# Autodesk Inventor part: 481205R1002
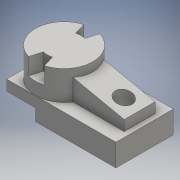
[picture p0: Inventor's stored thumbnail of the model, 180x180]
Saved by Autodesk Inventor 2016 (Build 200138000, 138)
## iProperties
Created: 2018-12
Part Number: 481205R1002
Material: 일반
Document SubType Name: Modeling
Designer: USER
Density: 1 g/cm^3
Appearance: 기본값
Author: USER
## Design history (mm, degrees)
sketch "스케치1"
  geometry: L1 (-78, 41)-(78, 41); L2 (78, 41)-(78, -41); L3 (78, -41)-(-78, -41); L4 (-78, -41)-(-78, 41); L5 (-78, 41)-(78, -41); L6 (78, 41)-(-78, -41); 1 further point
  constraints: 12 end point, 2 midpoint, 2 parallel, 1 horizontal, 1 perpendicular
  dimensions: "d5" = 82 distance of L1.end L2.end; "d6" = 156 distance of L2.end L3.end
extrude "돌출1" new body sketch "스케치1" distance "d7" = 15; taper "d8" = 0 deg
sketch "스케치2"
  geometry: L1 (78, 41)-(-78, 41) reference; L2 (-78, -41)-(78, -41) reference; L3 (-78, 41)-(37, 41); L4 (37, 41)-(37, -41); L5 (37, -41)-(-78, -41); L6 (-78, -41)-(-78, 41); 2 further points
  constraints: 8 end point, 2 parallel, 1 horizontal, 1 horizontal alignment, 1 midpoint, 1 perpendicular, 1 point on line
  dimensions: "d9" = 82 distance of L5.end L1.end (derived); "d10" = 115 distance of L1.end L3.end
extrude "돌출2" join sketch "스케치2" distance "d11" = 17; taper "d12" = 0 deg
node "작업 평면1"
sketch "스케치4"
  geometry: L1 (78, 0)-(-78, 0) reference; L2 (37, -15)-(37, -32) reference; L3 (78, -15)-(37, -15) reference; L4 (37, -15)-(37, 43.573); L5 (78, 0)-(78, 42); L6 (78, 42)-(37, 42); L7 (78, 0)-(37, 0); 1 further point
  constraints: 8 end point, 4 point on line, 2 vertical, 1 perpendicular
  dimensions: "d14" = 41 distance from line of L2 L1.start (derived); "d15" = 82 diameter of L5 L4; "d16" = 42 distance of L5.start L5.end
revolve "회전1" sketch "스케치4" stored, may be unused: angle "d17" = 90 deg
sketch "스케치5"
  geometry: L1 (0, 41)-(0, -41) reference; L2 (6.615, 23.07)-(11.301, 39.412); L3 (-6.615, 23.07)-(-11.301, 39.412); L4 (-58.467, 0)-(58.467, 0); C1 r 41 at (0, 0); C2 r 24 at (0, 0); A1 r 41 centre (0, 0) between (0, 41) and (0, -41) reference; A2 r 41 centre (0, 0) between (11.301, 39.412) and (-11.301, 39.412); A3 r 24 centre (0, 0) between (6.615, 23.07) and (-6.615, 23.07); A4 r 24 centre (0, 0) between (-6.615, -23.07) and (6.615, -23.07); 5 further points
  constraints: 7 point on circle, 6 end point, 5 centre point, 3 coincident, 3 point on line, 2 midpoint, 2 symmetric about line, 1 horizontal, 7 other
  dimensions: "d19" = 16 deg angle of L3 L1; "d20" = 16 deg angle of L2 L1; "d21" = 24 radius of A3; "d22" = 48 diameter of C2
extrude "돌출3" cut sketch "스케치5" distance "d23" = 24; taper "d24" = 0 deg
sketch "스케치6"
  geometry: L1 (48.301, -39.412)-(43.615, -23.07) reference; L2 (30.385, -23.07)-(25.699, -39.412) reference; L3 (25.699, 39.412)-(30.385, 23.07) reference; L4 (43.615, 23.07)-(48.301, 39.412) reference; C1 r 16 at (37, 0); A1 r 24 centre (37, 0) between (30.385, -23.07) and (43.615, -23.07) reference; A2 r 41 centre (37, 0) between (25.699, 39.412) and (25.699, -39.412) reference; A3 r 24 centre (37, 0) between (43.615, 23.07) and (30.385, 23.07) reference; A4 r 41 centre (37, 0) between (48.301, -39.412) and (48.301, 39.412) reference; 1 further point
  constraints: 1 centre point, 1 coincident
  dimensions: "d25" = 32 diameter of C1
extrude "돌출4" cut sketch "스케치6" distance "d26" = 15; taper "d27" = 0 deg
sketch "스케치9"
  geometry: C1 r 22 at (48.923, 0); 1 further point
  constraints: 1 centre point, 1 horizontal alignment
  dimensions: "d31" = 44 diameter of C1
extrude "돌출5" join sketch "스케치9" distance "d32" = 15; taper "d33" = 0 deg
node "작업 평면3"
sketch "스케치8"
  geometry: L1 (37, 0)-(-78, 0) reference; L2 (-48, 29.076)-(-48, -15.681); L3 (-26.923, 15)-(-70.923, 15) reference; L4 (-70.923, 15)-(37, 37.94); L5 (-70.923, 0)-(-70.923, 15) reference; L6 (78, 0)-(37, 0) reference; L7 (37, 0)-(37, 37.94); 2 further points
  constraints: 6 end point, 2 vertical
  dimensions: "d30" = 30 horizontal distance of L1.end L2.end; "d34" = 78 deg angle of L5 L4
extrude "돌출6" join sketch "스케치8" stored distance "d35" = 44; taper "d36" = 0 deg
sketch "스케치10"
  geometry: C1 r 12 at (48.213, 0); 1 further point
  constraints: 1 centre point, 1 horizontal alignment
  dimensions: "d37" = 24 diameter of C1
extrude "돌출7" cut sketch "스케치10" distance "d38" = 44; taper "d39" = 0 deg
node "솔리드1"
mirror "대칭1"
node "투영된 루프1"
other parameters: "d13" = 0, "d18" = 48, "d29" = 0
